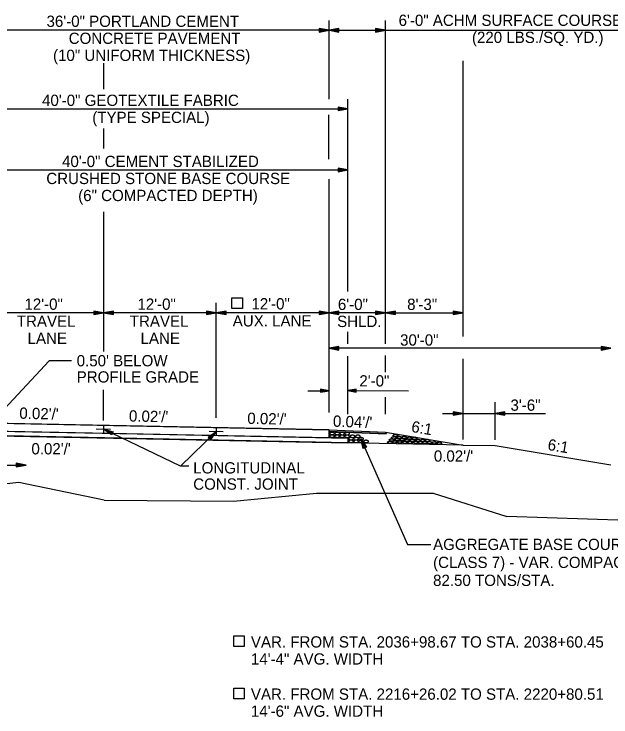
# Model space of a CAD drawing. Extents: x 1734743 to 1735935, y 759845 to 763831.
# Drawn here: x 1735800.2 to 1735863.7, y 760548.6 to 760623.4 of the extents above; entities that cross this region are included whole.
import ezdxf

# ---------------------------------------------------------------- set-up
doc = ezdxf.new("R2010")
doc.units = 0
for name, color, linetype in [('1', 7, 'Continuous'), ('10', 7, 'Continuous'), ('19', 7, 'Continuous'), ('8', 7, 'Continuous'), ('Level 1', 7, 'Continuous'), ('R_Draft', 7, 'Continuous'), ('R_Prop Surface', 7, 'Continuous')]:
    doc.layers.add(name, color=color, linetype=linetype)

# ---------------------------------------------------------------- blocks, each defined once
blk = doc.blocks.new('TM')
at = {"layer": '8'}
for p, q in [((-120.309, 21.181), (-119.787, -20.829)), ((0, 0), (-120.309, 21.181)), ((-31.382, 2.945), (-120.176, 10.512)), ((-119.787, -20.829), (0, 0)), ((-119.911, -10.826), (-31.307, -3.057))]:
    blk.add_line(p, q, dxfattribs=at)
blk = doc.blocks.new('ROCKS')
at = {"layer": '1'}
blk.add_spline([(0.013, 0.06), (0.053, 0.053), (0.107, 0.033), (0.133, 0.013), (0.133, -0.007), (0.12, -0.033), (0.107, -0.04), (0.073, -0.053), (0.033, -0.067), (0.013, -0.067), (-0.02, -0.06), (-0.06, -0.053), (-0.087, -0.047), (-0.113, -0.02), (-0.113, -0.007), (-0.107, 0.02), (-0.087, 0.033), (-0.067, 0.047), (-0.033, 0.053), (-0.02, 0.06), (0.013, 0.06)], degree=3, dxfattribs=at)

msp = doc.modelspace()

# ---------------------------------------------------------------- linework, layer by layer
at = {"layer": '10'}
for points in [[(1735824.491, 760593.226), (1735824.491, 760592.101), (1735823.366, 760592.101), (1735823.366, 760593.226)], [(1735824.682, 760557.248), (1735824.682, 760556.123), (1735823.557, 760556.123), (1735823.557, 760557.248)], [(1735824.682, 760551.693), (1735824.682, 760550.568), (1735823.557, 760550.568), (1735823.557, 760551.693)]]:
    msp.add_lwpolyline(points, close=True, dxfattribs=at)
at = {"layer": '19'}
for p, q in [((1735833.702, 760614.381), (1735833.702, 760622.74)), ((1735839.702, 760588.336), (1735839.702, 760622.74)), ((1735833.702, 760621.695), (1735797.721, 760621.695)), ((1735832.652, 760621.878), (1735832.652, 760621.511)), ((1735833.702, 760621.695), (1735832.652, 760621.878)), ((1735833.422, 760621.721), (1735832.652, 760621.782)), ((1735832.652, 760621.511), (1735833.702, 760621.695)), ((1735832.652, 760621.598), (1735833.422, 760621.668)), ((1735834.752, 760621.878), (1735833.702, 760621.695)), ((1735833.702, 760621.695), (1735834.752, 760621.511)), ((1735833.702, 760621.695), (1735839.702, 760621.695)), ((1735834.752, 760621.782), (1735833.982, 760621.721)), ((1735833.982, 760621.668), (1735834.752, 760621.598)), ((1735834.752, 760621.511), (1735834.752, 760621.878)), ((1735838.652, 760621.878), (1735838.652, 760621.511)), ((1735839.702, 760621.695), (1735838.652, 760621.878)), ((1735839.422, 760621.721), (1735838.652, 760621.782)), ((1735838.652, 760621.511), (1735839.702, 760621.695)), ((1735838.652, 760621.598), (1735839.422, 760621.668)), ((1735839.702, 760621.695), (1735874.364, 760621.695)), ((1735847.97, 760592.691), (1735847.97, 760618.465)), ((1735809.721, 760615.434), (1735809.721, 760618.188)), ((1735835.701, 760593.915), (1735835.701, 760614.381)), ((1735795.721, 760613.335), (1735835.701, 760613.335)), ((1735834.651, 760613.519), (1735834.651, 760613.152)), ((1735835.701, 760613.335), (1735834.651, 760613.519)), ((1735835.421, 760613.362), (1735834.651, 760613.423)), ((1735834.651, 760613.152), (1735835.701, 760613.335)), ((1735834.651, 760613.239), (1735835.421, 760613.309)), ((1735833.692, 760607.99), (1735833.692, 760612.697)), ((1735809.721, 760609.109), (1735809.721, 760611.243)), ((1735795.721, 760606.833), (1735835.701, 760606.833)), ((1735834.651, 760607.017), (1735834.651, 760606.65)), ((1735835.701, 760606.833), (1735834.651, 760607.017)), ((1735835.421, 760606.86), (1735834.651, 760606.921)), ((1735834.651, 760606.65), (1735835.701, 760606.833)), ((1735834.651, 760606.737), (1735835.421, 760606.807)), ((1735833.701, 760592.691), (1735833.701, 760605.841)), ((1735809.721, 760587.506), (1735809.721, 760602.367)), ((1735821.701, 760580.448), (1735821.701, 760592.691)), ((1735833.701, 760581.021), (1735833.701, 760592.691)), ((1735847.97, 760589.118), (1735847.97, 760592.691)), ((1735809.701, 760591.641), (1735797.701, 760591.641)), ((1735808.651, 760591.825), (1735808.651, 760591.457)), ((1735809.701, 760591.641), (1735808.651, 760591.825)), ((1735809.421, 760591.667), (1735808.651, 760591.729)), ((1735808.651, 760591.457), (1735809.701, 760591.641)), ((1735808.651, 760591.545), (1735809.421, 760591.615)), ((1735810.751, 760591.825), (1735809.701, 760591.641)), ((1735833.701, 760591.641), (1735809.701, 760591.641)), ((1735809.701, 760591.641), (1735810.751, 760591.457)), ((1735810.751, 760591.729), (1735809.981, 760591.667)), ((1735809.981, 760591.615), (1735810.751, 760591.545)), ((1735810.751, 760591.457), (1735810.751, 760591.825)), ((1735820.651, 760591.825), (1735820.651, 760591.457)), ((1735821.701, 760591.641), (1735820.651, 760591.825)), ((1735821.421, 760591.667), (1735820.651, 760591.729)), ((1735820.651, 760591.457), (1735821.701, 760591.641)), ((1735820.651, 760591.545), (1735821.421, 760591.615)), ((1735822.751, 760591.825), (1735821.701, 760591.641)), ((1735821.701, 760591.641), (1735822.751, 760591.457)), ((1735822.751, 760591.729), (1735821.981, 760591.667)), ((1735821.981, 760591.615), (1735822.751, 760591.545)), ((1735822.751, 760591.457), (1735822.751, 760591.825)), ((1735832.651, 760591.825), (1735832.651, 760591.457)), ((1735833.701, 760591.641), (1735832.651, 760591.825)), ((1735833.421, 760591.667), (1735832.651, 760591.729)), ((1735832.651, 760591.457), (1735833.701, 760591.641)), ((1735832.651, 760591.545), (1735833.421, 760591.615)), ((1735834.751, 760591.825), (1735833.701, 760591.641)), ((1735839.702, 760591.64), (1735833.701, 760591.641)), ((1735833.701, 760591.641), (1735834.751, 760591.457)), ((1735834.751, 760591.729), (1735833.981, 760591.667)), ((1735833.981, 760591.615), (1735834.751, 760591.545)), ((1735834.751, 760591.457), (1735834.751, 760591.825)), ((1735838.652, 760591.824), (1735838.652, 760591.457)), ((1735839.702, 760591.64), (1735838.652, 760591.824)), ((1735839.422, 760591.667), (1735838.652, 760591.728)), ((1735838.652, 760591.457), (1735839.702, 760591.64)), ((1735838.652, 760591.544), (1735839.422, 760591.614)), ((1735840.752, 760591.824), (1735839.702, 760591.64)), ((1735839.702, 760591.64), (1735840.752, 760591.457)), ((1735839.702, 760591.64), (1735847.97, 760591.64)), ((1735840.752, 760591.728), (1735839.982, 760591.667)), ((1735839.982, 760591.614), (1735840.752, 760591.544)), ((1735840.752, 760591.457), (1735840.752, 760591.824)), ((1735846.92, 760591.824), (1735846.92, 760591.457)), ((1735847.97, 760591.64), (1735846.92, 760591.824)), ((1735847.69, 760591.667), (1735846.92, 760591.728)), ((1735846.92, 760591.457), (1735847.97, 760591.64)), ((1735846.92, 760591.544), (1735847.69, 760591.614)), ((1735835.7, 760588.336), (1735835.7, 760589.605)), ((1735834.751, 760588.042), (1735833.701, 760587.858)), ((1735863.691, 760587.858), (1735833.701, 760587.858)), ((1735833.701, 760587.858), (1735834.751, 760587.675)), ((1735834.751, 760587.946), (1735833.981, 760587.885)), ((1735833.981, 760587.832), (1735834.751, 760587.762)), ((1735834.751, 760587.675), (1735834.751, 760588.042)), ((1735862.641, 760588.042), (1735862.641, 760587.675)), ((1735863.691, 760587.858), (1735862.641, 760588.042)), ((1735863.411, 760587.885), (1735862.641, 760587.946)), ((1735862.641, 760587.675), (1735863.691, 760587.858)), ((1735862.641, 760587.762), (1735863.411, 760587.832)), ((1735835.7, 760580.833), (1735835.7, 760587.035)), ((1735839.701, 760585.308), (1735839.701, 760587.091)), ((1735847.97, 760578.151), (1735847.97, 760586.721)), ((1735809.701, 760580.163), (1735809.701, 760583.436)), ((1735831.425, 760583.344), (1735833.693, 760583.342)), ((1735832.806, 760583.5), (1735832.806, 760583.187)), ((1735833.701, 760583.344), (1735832.806, 760583.5)), ((1735833.462, 760583.366), (1735832.806, 760583.418)), ((1735832.806, 760583.187), (1735833.701, 760583.344)), ((1735832.806, 760583.262), (1735833.462, 760583.321)), ((1735836.595, 760583.505), (1735835.7, 760583.348)), ((1735835.7, 760583.348), (1735842.149, 760583.344)), ((1735835.7, 760583.348), (1735836.595, 760583.192)), ((1735836.595, 760583.43), (1735835.939, 760583.371)), ((1735835.939, 760583.326), (1735836.595, 760583.274)), ((1735836.595, 760583.192), (1735836.595, 760583.505)), ((1735839.701, 760580.833), (1735839.701, 760582.659)), ((1735851.368, 760578.129), (1735851.368, 760582.118)), ((1735846.92, 760581.095), (1735846.92, 760580.728)), ((1735847.97, 760580.912), (1735846.92, 760581.095)), ((1735847.69, 760580.938), (1735846.92, 760580.999)), ((1735852.418, 760581.095), (1735851.368, 760580.912)), ((1735852.418, 760580.999), (1735851.648, 760580.938)), ((1735852.418, 760580.728), (1735852.418, 760581.095)), ((1735845.777, 760580.912), (1735856.718, 760580.912)), ((1735846.92, 760580.728), (1735847.97, 760580.912)), ((1735846.92, 760580.815), (1735847.69, 760580.885)), ((1735851.368, 760580.912), (1735852.418, 760580.728)), ((1735851.648, 760580.885), (1735852.418, 760580.815)), ((1735797.702, 760579.902), (1735833.702, 760579.182)), ((1735797.685, 760579.069), (1735833.702, 760578.348)), ((1735810.564, 760578.638), (1735809.701, 760579.258)), ((1735809.701, 760579.258), (1735810.726, 760578.965)), ((1735810.601, 760578.716), (1735809.939, 760579.111)), ((1735809.96, 760579.156), (1735810.68, 760578.884)), ((1735810.726, 760578.965), (1735810.564, 760578.638)), ((1735820.823, 760578.415), (1735821.701, 760579.014)), ((1735820.884, 760578.353), (1735821.481, 760578.84)), ((1735821.516, 760578.805), (1735821.014, 760578.221)), ((1735821.701, 760579.014), (1735821.075, 760578.151)), ((1735833.702, 760579.182), (1735839.702, 760578.942)), ((1735833.702, 760579.182), (1735833.702, 760578.348)), ((1735833.702, 760579.015), (1735839.787, 760578.772)), ((1735839.702, 760578.942), (1735847.97, 760577.564)), ((1735797.675, 760578.569), (1735833.675, 760577.849)), ((1735797.701, 760578.569), (1735835.7, 760577.809)), ((1735821.075, 760578.151), (1735820.823, 760578.415)), ((1735835.701, 760578.308), (1735833.702, 760578.348)), ((1735835.701, 760578.308), (1735835.701, 760577.808)), ((1735837.09, 760578.235), (1735842.056, 760566.989)), ((1735837.346, 760577.203), (1735837.09, 760578.235)), ((1735837.09, 760578.235), (1735837.681, 760577.348)), ((1735847.977, 760577.563), (1735833.675, 760577.849)), ((1735837.425, 760577.239), (1735837.176, 760577.968)), ((1735837.221, 760577.989), (1735837.594, 760577.315)), ((1735837.681, 760577.348), (1735837.346, 760577.203)), ((1735847.97, 760577.564), (1735851.385, 760577.496)), ((1735851.385, 760577.496), (1735863.701, 760575.443)), ((1735798.043, 760575.431), (1735801.464, 760575.431)), ((1735800.684, 760573.577), (1735789.496, 760572.309)), ((1735809.784, 760571.71), (1735800.684, 760573.577)), ((1735823.527, 760571.595), (1735832.379, 760572.43)), ((1735832.379, 760572.43), (1735844.79, 760572.43)), ((1735844.79, 760572.43), (1735852.619, 760569.946)), ((1735809.784, 760571.71), (1735823.527, 760571.595)), ((1735872.447, 760569.315), (1735852.619, 760569.946)), ((1735842.056, 760566.989), (1735844.537, 760566.989))]:
    msp.add_line(p, q, dxfattribs=at)
for points in [[(1735806.283, 760586.514), (1735803.928, 760586.514), (1735797.702, 760579.902)], [(1735795.685, 760578.529), (1735795.685, 760579.029), (1735797.702, 760579.068), (1735835.701, 760578.308), (1735835.701, 760577.808), (1735835.701, 760577.808), (1735835.701, 760577.808), (1735797.675, 760578.569), (1735795.685, 760578.529)], [(1735818.76, 760575.3), (1735817.884, 760575.3), (1735809.701, 760579.258)], [(1735817.884, 760575.3), (1735817.884, 760575.3), (1735821.701, 760579.014)], [(1735839.787, 760578.772), (1735833.702, 760579.015), (1735833.702, 760579.015), (1735833.702, 760579.182), (1735833.702, 760579.182), (1735833.702, 760579.182), (1735839.702, 760578.942), (1735839.702, 760578.942), (1735839.702, 760578.942), (1735839.787, 760578.772), (1735839.787, 760578.772), (1735839.787, 760578.772)]]:
    msp.add_lwpolyline(points, dxfattribs=at)
msp.add_lwpolyline([(1735833.702, 760579.182), (1735797.702, 760579.902), (1735797.702, 760579.068), (1735833.702, 760578.348)], close=True, dxfattribs=at)
at = {"layer": 'R_Draft'}
for p, q in [((1735809.701, 760579.634), (1735809.701, 760578.883)), ((1735808.93, 760579.274), (1735810.448, 760579.243)), ((1735820.93, 760579.03), (1735822.448, 760578.999)), ((1735821.701, 760579.39), (1735821.701, 760578.639))]:
    msp.add_line(p, q, dxfattribs=at)
at = {"layer": 'R_Prop Surface'}
msp.add_line((1735839.702, 760578.942), (1735839.787, 760578.772), dxfattribs=at)

# ---------------------------------------------------------------- block references
at = {"layer": '19', "xscale": 0.008761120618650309, "yscale": 0.008761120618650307, "rotation": -0.7994241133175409}
msp.add_blockref('TM', (1735801.465, 760575.427), dxfattribs=at)
at = {"layer": 'Level 1', "xscale": 2.011654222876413}
for p, yscale, rotation in [((1735834.008, 760578.793), 2.011654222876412, 1.33680650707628), ((1735834.551, 760578.788), 2.011654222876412, 1.33680650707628), ((1735835.073, 760578.784), 2.011654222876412, 1.33680650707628), ((1735835.615, 760578.779), 2.011654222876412, 1.33680650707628), ((1735834, 760578.513), 2.011654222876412, 1.33680650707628), ((1735834.543, 760578.508), 2.011654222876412, 1.33680650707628), ((1735835.065, 760578.504), 2.011654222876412, 1.33680650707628), ((1735835.608, 760578.499), 2.011654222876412, 1.33680650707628), ((1735836.017, 760577.964), 2.011654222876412, 1.33680650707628), ((1735836.025, 760578.244), 2.011654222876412, 1.33680650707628), ((1735836.175, 760578.499), 2.011654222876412, 1.33680650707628), ((1735836.56, 760577.959), 2.011654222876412, 1.33680650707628), ((1735836.568, 760578.239), 2.011654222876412, 1.33680650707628), ((1735836.746, 760578.499), 2.011654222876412, 1.33680650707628), ((1735837.082, 760577.955), 2.011654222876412, 1.33680650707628), ((1735837.09, 760578.235), 2.011654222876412, 1.33680650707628), ((1735837.625, 760577.95), 2.011654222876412, 1.33680650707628), ((1735840.201, 760577.86), -2.011654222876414, 178.00441377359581), ((1735840.378, 760578.105), -2.011654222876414, 178.00441377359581), ((1735840.61, 760578.33), -2.011654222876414, 178.00441377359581), ((1735840.698, 760577.895), -2.011654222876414, 178.00441377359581), ((1735840.784, 760578.569), -2.011654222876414, 178.00441377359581), ((1735840.962, 760578.133), -2.011654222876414, 178.00441377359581), ((1735841.185, 760578.375), -2.011654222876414, 178.00441377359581), ((1735841.229, 760577.894), -2.011654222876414, 178.00441377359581), ((1735841.488, 760578.13), -2.011654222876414, 178.00441377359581), ((1735841.708, 760578.383), -2.011654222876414, 178.00441377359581), ((1735841.763, 760577.853), -2.011654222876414, 178.00441377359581), ((1735842.002, 760578.081), -2.011654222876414, 178.00441377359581), ((1735842.261, 760578.304), -2.011654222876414, 178.00441377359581), ((1735842.323, 760577.855), -2.011654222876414, 178.00441377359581), ((1735842.575, 760578.06), -2.011654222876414, 178.00441377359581), ((1735842.808, 760578.294), -2.011654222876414, 178.00441377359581), ((1735842.931, 760577.853), -2.011654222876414, 178.00441377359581), ((1735843.183, 760578.058), -2.011654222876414, 178.00441377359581), ((1735843.676, 760578.05), -2.011654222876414, 178.00441377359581), ((1735844.186, 760578.049), -2.011654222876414, 178.00441377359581), ((1735843.421, 760577.836), -2.011654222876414, 178.00441377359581), ((1735843.918, 760577.827), -2.011654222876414, 178.00441377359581), ((1735844.414, 760577.815), -2.011654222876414, 178.00441377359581), ((1735844.913, 760577.799), -2.011654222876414, 178.00441377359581), ((1735845.442, 760577.768), -2.011654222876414, 178.00441377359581)]:
    msp.add_blockref('ROCKS', p, dxfattribs=dict(at, yscale=yscale, rotation=rotation))

# ---------------------------------------------------------------- texts
at = {"layer": '19'}
for s, p in [('36\'-0" PORTLAND CEMENT', (1735803.633, 760622.059)), ('6\'-0" ACHM SURFACE COURSE (1/2")', (1735841.101, 760622.162)), ('CONCRETE PAVEMENT', (1735805.995, 760620.247)), ('(220 LBS./SQ. YD.)', (1735848.905, 760620.349)), ('(10" UNIFORM THICKNESS)', (1735804.328, 760618.434)), ('40\'-0" GEOTEXTILE FABRIC', (1735803.158, 760613.647)), ('(TYPE SPECIAL)', (1735808.501, 760611.834)), ('40\'-0" CEMENT STABILIZED ', (1735805.287, 760607.145)), ('CRUSHED STONE BASE COURSE', (1735803.61, 760605.332)), ('(6" COMPACTED DEPTH)', (1735807.002, 760603.52)), ('12\'-0"', (1735801.283, 760591.956)), ('12\'-0"', (1735813.306, 760591.956)), ('12\'-0" ', (1735825.437, 760591.995)), ('6\'-0"', (1735834.639, 760591.933)), ('8\'-3"', (1735842.01, 760591.937)), ('TRAVEL', (1735800.475, 760590.144)), ('TRAVEL', (1735812.498, 760590.144)), ('AUX. LANE', (1735823.448, 760590.182)), ('SHLD.', (1735834.558, 760590.12)), ('LANE', (1735801.618, 760588.331)), ('LANE', (1735813.641, 760588.331)), ('30\'-0"', (1735841.259, 760588.142)), ("0.50' BELOW", (1735806.845, 760585.936)), ('PROFILE GRADE', (1735806.845, 760584.211)), ('2\'-0"', (1735836.925, 760583.793)), ('3\'-6"', (1735853.008, 760581.208)), ("0.02'/'", (1735802.026, 760576.567)), ("0.02'/'", (1735844.85, 760575.793)), ('LONGITUDINAL', (1735819.246, 760574.534)), ('CONST. JOINT', (1735819.246, 760572.809))]:
    msp.add_text(s, height=1.2, dxfattribs=at).set_placement(p)
for s, rotation, p in [("0.02'/'", 358.63856, (1735800.729, 760580.364)), ("0.02'/'", 358.63856, (1735812.391, 760580.069)), ("0.02'/'", 358.63856, (1735824.985, 760579.817)), ("0.04'/'", 357.83981, (1735834.095, 760579.522)), ('6:1', 350.54888, (1735842.389, 760578.964)), ('6:1', 350.54888, (1735856.896, 760577.047)), ('AGGREGATE BASE COURSE', 360, (1735844.769, 760566.389)), ('(CLASS 7) - VAR. COMPACTED DEPTH', 360, (1735844.769, 760564.477)), ('82.50 TONS/STA.', 360, (1735844.769, 760562.566)), ('VAR. FROM STA. 2036+98.67 TO STA. 2038+60.45', 359.99538, (1735825.384, 760556.012)), ('14\'-4" AVG. WIDTH', 359.99538, (1735825.384, 760554.199)), ('VAR. FROM STA. 2216+26.02 TO STA. 2220+80.51', 359.99538, (1735825.384, 760550.457)), ('14\'-6" AVG. WIDTH', 359.99538, (1735825.384, 760548.644))]:
    msp.add_text(s, height=1.2, rotation=rotation, dxfattribs=at).set_placement(p)

doc.saveas('drawing.dxf')
